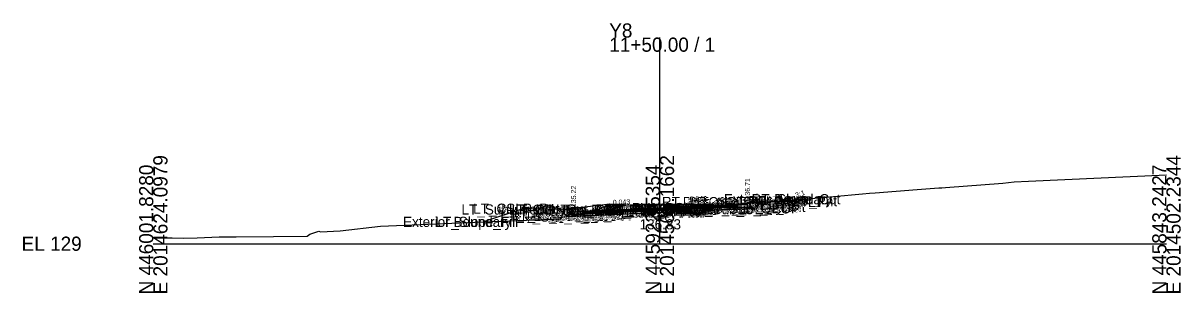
# Model space of a CAD drawing. Extents: x -26 to 1403, y -10 to 8043.
# Drawn here: x -25.7 to 202.8, y 2990.3 to 3043.5 of the extents above; entities that cross this region are included whole.
import ezdxf

# ---------------------------------------------------------------- set-up
doc = ezdxf.new("R2010")
doc.units = 0
for name, color, linetype in [('Default', 7, 'Continuous'), ('Exist Cross Section Cell', 7, 'Continuous'), ('Exist XS Center Line Elevation Label', 7, 'Continuous'), ('Exist XS Ground Line', 7, 'Continuous'), ('Prop CMT Conc Surface', 7, 'Continuous'), ('Prop CMT Concrete Structures', 7, 'Continuous'), ('Prop CMT Pvmt Course 1', 7, 'Continuous'), ('Prop CMT Pvmt Course 1 CG', 7, 'Continuous'), ('Prop CMT Pvmt Course 2', 7, 'Continuous'), ('Prop CMT Pvmt Course 3', 7, 'Continuous'), ('Prop CMT Pvmt Surface', 7, 'Continuous'), ('Prop CMT Slope Grass', 7, 'Continuous'), ('Prop CMT Subgrade Earthwork', 7, 'Continuous'), ('Prop XS Earthwork Shape', 7, 'Continuous'), ('Prop XS Hydro Elevations', 7, 'Continuous'), ('Prop XS SE Text', 7, 'Continuous'), ('Prop XS Side Slope Text', 7, 'Continuous'), ('Scratch_Level_0', 7, 'Continuous')]:
    doc.layers.add(name, color=color, linetype=linetype)

msp = doc.modelspace()

# ---------------------------------------------------------------- linework, layer by layer
at = {"layer": 'Exist Cross Section Cell'}
for p, q in [((100, 3000), (100, 3040.68)), ((0, 3000), (100, 3000)), ((100, 3000), (200, 3000))]:
    msp.add_line(p, q, dxfattribs=at)
at = {"layer": 'Exist XS Ground Line'}
msp.add_lwpolyline([(0, 3001.19), (3.73, 3001.13), (5.87, 3001.12), (8.66, 3001.19), (13, 3001.37), (16.34, 3001.34), (23.71, 3001.44), (30.4, 3001.49), (30.9, 3001.89), (32.69, 3002.47), (33.01, 3002.37), (36.89, 3002.54), (44.87, 3003.44), (62.08, 3004.19), (62.78, 3004.21), (63.48, 3004.24), (80.43, 3004.94), (80.63, 3005.22), (81.1, 3006.83), (88.03, 3007.58), (90.07, 3007.86), (90.97, 3007.56), (100, 3007.83), (100.49, 3007.85), (101.04, 3007.87), (111.44, 3007.62), (111.96, 3007.61), (113.52, 3007.72), (127.12, 3008.67), (129.86, 3008.92), (134.25, 3009.3), (139.97, 3009.82), (141.38, 3009.95), (142.47, 3010.06), (150.78, 3010.68), (155.08, 3011), (155.65, 3011.04), (156.38, 3011.09), (167.7, 3011.97), (169.91, 3012.19), (172.79, 3012.33), (200, 3013.56)], dxfattribs=at)
at = {"layer": 'Prop CMT Conc Surface'}
for points in [[(115.3, 3007.7), (117.3, 3007.71)], [(117.3, 3007.71), (117.31, 3008.21), (117.81, 3008.21)], [(82.96, 3006.22), (82.96, 3006.72), (82.46, 3006.72)], [(84.96, 3006.39), (82.96, 3006.22)]]:
    msp.add_lwpolyline(points, dxfattribs=at)
at = {"layer": 'Prop CMT Concrete Structures'}
for points in [[(115.3, 3007.7), (117.3, 3007.71), (117.31, 3008.21), (117.81, 3008.21)], [(117.81, 3008.21), (117.8, 3007.23), (115.3, 3007.12)], [(115.3, 3007.12), (115.3, 3007.7)], [(84.96, 3006.39), (82.96, 3006.22), (82.96, 3006.72), (82.46, 3006.72)], [(82.46, 3006.72), (82.46, 3005.69), (84.96, 3005.8)], [(84.96, 3005.8), (84.96, 3006.39)]]:
    msp.add_lwpolyline(points, dxfattribs=at)
at = {"layer": 'Prop CMT Pvmt Course 1'}
for points in [[(100, 3007.04), (115.3, 3007.7)], [(115.3, 3007.7), (115.3, 3007.45)], [(100, 3007.04), (84.96, 3006.39)], [(84.96, 3006.14), (100, 3006.79)], [(84.96, 3006.39), (84.96, 3006.14)], [(115.3, 3007.45), (100, 3006.79)], [(100, 3006.79), (100, 3007.04)], [(100, 3006.79), (100, 3007.04)]]:
    msp.add_lwpolyline(points, dxfattribs=at)
msp.add_lwpolyline([(100, 3006.79), (100, 3006.91), (100, 3006.91), (100, 3006.79)], close=True, dxfattribs=at)
msp.add_lwpolyline([(100, 3006.79), (100, 3006.91), (100, 3006.91), (100, 3006.79)], close=True, dxfattribs=at)
at = {"layer": 'Prop CMT Pvmt Course 1 CG'}
for points in [[(84.96, 3005.8), (81.96, 3005.67), (81.65, 3005.37)], [(81.65, 3005.37), (84.96, 3005.51)], [(84.96, 3005.51), (84.96, 3005.8)], [(115.3, 3007.12), (118.3, 3007.25), (118.58, 3006.97)], [(115.3, 3006.83), (115.3, 3007.12)], [(118.58, 3006.97), (115.3, 3006.83)]]:
    msp.add_lwpolyline(points, dxfattribs=at)
at = {"layer": 'Prop CMT Pvmt Course 2'}
for points in [[(100, 3006.79), (84.96, 3006.14)], [(84.96, 3005.89), (100, 3006.54)], [(84.96, 3006.14), (84.96, 3005.89)], [(100, 3006.79), (115.3, 3007.45)], [(115.3, 3007.2), (100, 3006.54)], [(100, 3006.54), (100, 3006.79)], [(100, 3006.54), (100, 3006.79)], [(115.3, 3007.45), (115.3, 3007.2)]]:
    msp.add_lwpolyline(points, dxfattribs=at)
at = {"layer": 'Prop CMT Pvmt Course 3'}
for points in [[(100, 3006.54), (84.96, 3005.89)], [(84.96, 3005.51), (100, 3006.16)], [(84.96, 3005.89), (84.96, 3005.51)], [(100, 3006.54), (115.3, 3007.2)], [(115.3, 3006.83), (100, 3006.16)], [(100, 3006.16), (100, 3006.54)], [(100, 3006.16), (100, 3006.54)], [(115.3, 3007.2), (115.3, 3006.83)]]:
    msp.add_lwpolyline(points, dxfattribs=at)
at = {"layer": 'Prop CMT Pvmt Surface'}
for points in [[(100, 3007.04), (115.3, 3007.7)], [(100, 3007.04), (84.96, 3006.39)]]:
    msp.add_lwpolyline(points, dxfattribs=at)
at = {"layer": 'Prop CMT Slope Grass'}
for points in [[(117.81, 3008.21), (127.31, 3008.4), (128.49, 3008.79)], [(82.46, 3006.72), (72.96, 3006.91), (65.16, 3004.31)]]:
    msp.add_lwpolyline(points, dxfattribs=at)
at = {"layer": 'Prop CMT Subgrade Earthwork'}
for points in [[(115.3, 3006.83), (118.58, 3006.97), (119.86, 3008.25)], [(84.96, 3005.51), (81.65, 3005.37), (80.26, 3006.76)], [(100, 3006.16), (84.96, 3005.51)], [(100, 3006.16), (115.3, 3006.83)]]:
    msp.add_lwpolyline(points, dxfattribs=at)
at = {"layer": 'Prop XS Earthwork Shape'}
for points in [[(82.46, 3005.69), (84.96, 3005.8), (84.96, 3006.39), (100, 3007.04), (115.3, 3007.7), (115.3, 3007.12), (117.8, 3007.23), (117.81, 3008.02), (119.77, 3008.15), (118.58, 3006.97), (115.3, 3006.83), (100, 3006.16), (84.96, 3005.51), (81.65, 3005.37), (80.9, 3006.13), (81.08, 3006.75), (82.46, 3006.72)], [(84.96, 3006.39), (82.96, 3006.22), (82.96, 3006.72), (82.46, 3006.72), (81.08, 3006.75), (81.1, 3006.83), (88.03, 3007.58), (90.07, 3007.86), (90.97, 3007.56), (100, 3007.83), (100.49, 3007.85), (101.04, 3007.87), (111.44, 3007.62), (111.96, 3007.61), (113.52, 3007.72), (117.3, 3007.98), (117.3, 3007.71), (115.3, 3007.7), (100, 3007.04)], [(117.81, 3008.02), (117.8, 3007.23), (115.3, 3007.12), (115.3, 3007.7), (117.3, 3007.71), (117.3, 3007.98)], [(119.86, 3008.25), (121.63, 3008.28), (119.77, 3008.15)], [(121.63, 3008.28), (127.31, 3008.4), (128.49, 3008.79), (127.12, 3008.67)], [(80.26, 3006.76), (72.96, 3006.91), (65.16, 3004.31), (80.43, 3004.94), (80.63, 3005.22), (80.9, 3006.13)], [(82.46, 3005.69), (84.96, 3005.8), (84.96, 3006.39), (82.96, 3006.22), (82.96, 3006.72), (82.46, 3006.72)]]:
    msp.add_lwpolyline(points, close=True, dxfattribs=at)

# ---------------------------------------------------------------- texts
at = {"layer": 'Default'}
msp.add_text('-', height=0.0001, dxfattribs=at).set_placement((0, 3000))
at = {"layer": 'Exist Cross Section Cell'}
for s, p in [('Y8', (90, 3040.68)), ('11+50.00 / 1', (90, 3037.88)), ('EL 129', (-26, 2998.6))]:
    msp.add_text(s, height=2.8, dxfattribs=at).set_placement(p)
for s, p in [('E 2014624.0979', (2.8, 2990)), ('E 2014563.1662', (102.8, 2990)), ('E 2014502.2344', (202.8, 2990)), ('N 446001.8280', (0, 2990)), ('N 445922.5354', (100, 2990)), ('N 445843.2427', (200, 2990))]:
    msp.add_text(s, height=2.8, rotation=90, dxfattribs=at).set_placement(p)
at = {"layer": 'Exist XS Center Line Elevation Label'}
msp.add_text('136.83', height=2, dxfattribs=at).set_placement((95.99, 3002.83))
at = {"layer": 'Prop XS Hydro Elevations'}
for s, p in [('136.71', (117.8, 3008.71)), ('135.22', (83.46, 3007.22))]:
    msp.add_text(s, height=1, rotation=90, dxfattribs=at).set_placement(p)
at = {"layer": 'Prop XS SE Text'}
for p in [(90.71, 3007.64), (105.88, 3008.29)]:
    msp.add_text('0.043', height=1, rotation=2.4813, dxfattribs=at).set_placement(p)
at = {"layer": 'Prop XS Side Slope Text'}
for p in [(126.91, 3009.06), (68.07, 3006.07)]:
    msp.add_text('3:1', height=1, rotation=18.4332, dxfattribs=at).set_placement(p)
at = {"layer": 'Scratch_Level_0'}
for s, p in [('Exterior Boundary', (112.63, 3007.79)), ('RT_Slope_Cut', (118.08, 3007.79)), ('LT_Sub_Trench_Out_DLT', (60.83, 3005.76)), ('LT_CSLP_Pnt', (63.13, 3005.91)), ('LT_CG_Top_Face', (70.22, 3005.72)), ('LT_CG_Top_BOC', (70.74, 3005.72)), ('RT_PV2_OEEOP', (89.26, 3005.79)), ('RT_PV3_OEEOP', (89.26, 3005.54)), ('LT_PV2_OEEOP', (89.31, 3005.79)), ('LT_PV3_OEEOP', (89.31, 3005.54)), ('RT_PV1_OEEOP', (89.83, 3005.91)), ('LT_PV1_OEEOP', (89.87, 3005.91)), ('RT_PV2_IEEOP', (89.91, 3005.79)), ('LT_PV2_IEEOP', (89.95, 3005.79)), ('RT_PV1_IEEOP', (90.47, 3005.91)), ('LT_PV1_IEEOP', (90.52, 3005.91)), ('PV2_PGL', (93.91, 3005.79)), ('PV1_PGL', (94.47, 3006.04)), ('RT_Sub_Trench_Out_DLT', (100.38, 3007.25)), ('RT_CG_Top_Face', (104.52, 3007.21)), ('RT_CG1_Shelf_Out', (104.81, 3006.25)), ('RT_CG_Bot_IE', (105.17, 3006.12)), ('RT_Sub_OEOT', (105.34, 3005.83)), ('RT_PV2_OEOT', (105.43, 3006.45)), ('RT_PV3_OEOT', (105.43, 3006.2)), ('RT_CG_Top_Gut', (105.49, 3006.71)), ('RT_PV1_OEOT', (106, 3006.7)), ('RT_CG_Top_BOC', (106.04, 3007.21)), ('RT_CG_Bot_BOC', (106.07, 3006.23)), ('RT_Sub_OEOP', (108.65, 3005.97)), ('RT_CSLP_Pnt', (117.43, 3007.4)), ('Exterior Boundary', (49.3, 3003.31)), ('LT_Slope_Fill', (55.68, 3003.31)), ('LT_CG1_Shelf_Out', (68.51, 3004.67)), ('LT_CG_Bot_BOC', (70.77, 3004.69)), ('LT_CG_Top_Gut', (71.19, 3005.22)), ('LT_Sub_OEOP', (71.76, 3004.37)), ('LT_CG_Bot_IE', (74.87, 3004.8)), ('LT_Sub_OEOT', (75.04, 3004.51)), ('LT_PV2_OEOT', (75.13, 3005.14)), ('LT_PV3_OEOT', (75.13, 3004.89)), ('LT_PV1_OEOT', (75.7, 3005.39)), ('RT_Sub_OEEOP', (89.17, 3005.16)), ('LT_Sub_OEEOP', (89.21, 3005.16))]:
    msp.add_text(s, height=2, dxfattribs=at).set_placement(p)

doc.saveas('drawing.dxf')
